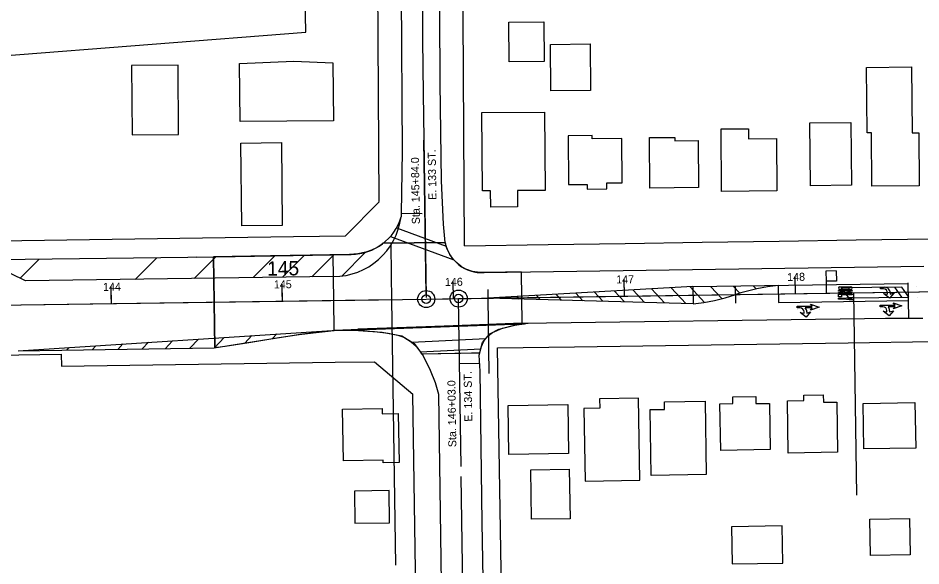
# Model space of a CAD drawing. Extents: x -2233 to 187241, y 4582 to 150524.
# Drawn here: x 114288 to 114816, y 59403 to 59724 of the extents above; entities that cross this region are included whole.
import ezdxf

# ---------------------------------------------------------------- set-up
doc = ezdxf.new("R2010")
doc.units = 0
for name, color, linetype in [('AP_X_Misc', 7, 'Continuous'), ('BLDG', 7, 'Continuous'), ('GE_X_CL_100', 7, 'Continuous'), ('GE_X_CL_20', 7, 'Continuous'), ('GE_X_CL_2000', 7, 'Continuous'), ('GE_X_CL_50', 7, 'Continuous'), ('PM_P_Cells', 7, 'Continuous'), ('PM_P_Channelizing_Line', 7, 'Continuous'), ('PM_P_CL_Double_Solid', 7, 'Continuous'), ('PM_P_Crosswalk', 7, 'Continuous'), ('PM_P_Edge_Line', 7, 'Continuous'), ('PM_P_Stop_Line', 7, 'Continuous'), ('PM_P_Text', 7, 'Continuous'), ('PM_P_Transverse_Line', 7, 'Continuous'), ('ROAD', 7, 'Continuous'), ('RW_X_Fee_RW', 7, 'Continuous'), ('SG_P_Detection', 7, 'Continuous')]:
    doc.layers.add(name, color=color, linetype=linetype)

msp = doc.modelspace()

# ---------------------------------------------------------------- linework, layer by layer
at = {"layer": 'AP_X_Misc'}
for p, q in [((114472.32, 59558.35), (114471.93, 59585.11)), ((114402.33, 59557.33), (114401.95, 59583.84)), ((114582.31, 59559.94), (114582.09, 59574.94)), ((114472.58, 59540.94), (114472.32, 59558.35)), ((114582.53, 59544.95), (114582.31, 59559.94)), ((114402.72, 59530.83), (114402.33, 59557.33)), ((114582.53, 59544.95), (114472.58, 59540.82))]:
    msp.add_line(p, q, dxfattribs=at)
for points in [[(114276.11, 59701.18), (114455.92, 59715.3), (114455.49, 59745.29), (114275.34, 59754.19)], [(114401.95, 59583.84), (114402.72, 59530.83), (114408.87, 59531.56), (114422.61, 59533.76), (114440.22, 59536.58), (114452.12, 59538.49), (114460.21, 59539.47), (114468.99, 59540.43), (114472.58, 59540.94), (114481.11, 59540.9), (114582.87, 59544.58), (114582.53, 59544.95), (114582.09, 59574.94), (114579.6, 59574.91), (114572.67, 59574.81), (114568.04, 59574.74), (114564.56, 59574.69), (114560.95, 59574.64), (114557.75, 59574.62), (114553.49, 59575.28), (114549.52, 59576.72), (114546.88, 59578.21), (114545.17, 59579.46), (114542.26, 59582.29), (114540.21, 59585.14), (114538.58, 59588.41), (114537.78, 59590.81), (114537.44, 59592.3), (114501.27, 59591.77), (114499.92, 59590.77), (114497.78, 59589.4), (114494.48, 59587.74), (114491.14, 59586.54), (114486.32, 59585.54), (114481.54, 59585.29), (114423.85, 59584.24)], [(114486.36, 59541.45), (114490.22, 59540.54), (114496.16, 59540.07), (114504.05, 59539.09), (114509.8, 59538.02), (114513.28, 59536.87), (114517.62, 59534.17), (114520.45, 59531.58), (114522.94, 59528.1), (114523.62, 59527.16), (114543.18, 59527.45), (114552.92, 59527.59), (114557.69, 59527.66), (114558.52, 59531), (114560.22, 59534.89), (114562.51, 59537.57), (114565.19, 59539.63), (114570.94, 59542.04), (114577.87, 59543.79), (114583.77, 59544.7), (114581.4, 59544.9), (114558.08, 59544.06), (114526.2, 59542.9)]]:
    msp.add_lwpolyline(points, close=True, dxfattribs=at)
at = {"layer": 'BLDG'}
for points in [[(114595.15, 59721.38), (114595.35, 59698.14), (114574.94, 59697.96), (114574.74, 59721.2)], [(114622.26, 59708.4), (114622.5, 59681.11), (114599.24, 59680.9), (114599.01, 59708.19)], [(114381.65, 59655.38), (114381.29, 59696.05), (114354.17, 59695.82), (114354.53, 59655.15)], [(114417.26, 59696.94), (114448.94, 59698.41), (114471.84, 59697.41), (114472.14, 59663.51), (114417.55, 59663.04)], [(114810.12, 59694.93), (114810.45, 59656.46), (114814.27, 59656.49), (114814.55, 59625.36), (114786.96, 59625.12), (114786.68, 59656.5), (114784.12, 59656.48), (114783.79, 59694.71)], [(114595.55, 59668.54), (114595.95, 59622.74), (114579.65, 59622.6), (114579.73, 59613.06), (114564.11, 59612.92), (114564.02, 59622.53), (114559.29, 59622.49), (114558.89, 59668.22)], [(114714.77, 59658.81), (114714.82, 59652.97), (114731.05, 59653.11), (114731.32, 59622.45), (114699.07, 59622.17), (114698.75, 59658.67)], [(114774.61, 59662.48), (114774.93, 59625.7), (114750.96, 59625.49), (114750.64, 59662.27)], [(114620.44, 59626.26), (114620.47, 59623.49), (114631.95, 59623.59), (114631.92, 59627.13), (114641.01, 59627.21), (114640.79, 59653.1), (114623.41, 59652.94), (114623.39, 59654.78), (114609.33, 59654.66), (114609.58, 59626.16)], [(114671.75, 59653.74), (114671.77, 59651.79), (114685.26, 59651.9), (114685.5, 59624.36), (114657.07, 59624.12), (114656.81, 59653.61)], [(114441.78, 59650.66), (114442.2, 59602.23), (114418.5, 59602.02), (114418.07, 59650.45)], [(114627.77, 59500.82), (114627.85, 59495.27), (114618.53, 59495.12), (114619.23, 59452.55), (114651.24, 59453.07), (114650.46, 59501.18)], [(114698.11, 59497.88), (114705.59, 59498), (114705.53, 59501.95), (114719.09, 59502.18), (114719.15, 59497.95), (114727.07, 59498.08), (114727.52, 59471.08), (114698.56, 59470.6)], [(114737.54, 59499.53), (114747.21, 59499.7), (114747.15, 59502.86), (114758.47, 59503.05), (114758.54, 59498.76), (114766.37, 59498.89), (114766.84, 59469.51), (114738.04, 59469.04)], [(114500.63, 59495.15), (114500.68, 59492.04), (114510, 59492.19), (114510.47, 59463.46), (114501.19, 59463.31), (114501.16, 59464.95), (114477.97, 59464.57), (114477.47, 59494.76)], [(114574.25, 59496.87), (114609.07, 59497.44), (114609.54, 59468.84), (114574.72, 59468.26)], [(114665.75, 59494.57), (114665.67, 59499.07), (114689.36, 59499.45), (114690.06, 59456.48), (114657.9, 59455.95), (114657.27, 59494.42)], [(114781.78, 59498.09), (114812.07, 59498.58), (114812.5, 59471.98), (114782.21, 59471.47)], [(114610.02, 59459.62), (114610.49, 59430.63), (114587.97, 59430.27), (114587.5, 59459.25)], [(114484.71, 59427.91), (114504.98, 59428.25), (114504.68, 59447.14), (114484.4, 59446.81)], [(114705.22, 59404.12), (114734.76, 59404.6), (114734.4, 59426.43), (114704.86, 59425.95)], [(114808.94, 59430.72), (114809.29, 59409.52), (114786.06, 59409.13), (114785.72, 59430.34)]]:
    msp.add_lwpolyline(points, close=True, dxfattribs=at)
at = {"layer": 'GE_X_CL_100'}
for p, q in [((114542.32, 59559.36), (114542.17, 59569.36)), ((114642.3, 59560.82), (114642.16, 59570.81)), ((114742.29, 59562.27), (114742.15, 59572.27)), ((114342.34, 59556.46), (114342.19, 59566.46)), ((114442.33, 59557.91), (114442.18, 59567.91))]:
    msp.add_line(p, q, dxfattribs=at)
for centre in [(114526.38, 59559.13), (114545.33, 59559.41), (114545.33, 59559.41)]:
    msp.add_circle(centre, 5, dxfattribs=at)
at = {"layer": 'GE_X_CL_20'}
for p, q in [((114524.63, 59679.24), (114526.36, 59560.13)), ((114545.33, 59559.41), (114849.04, 59563.82)), ((114245.36, 59555.05), (114526.38, 59559.13)), ((114526.38, 59559.13), (114545.33, 59559.41)), ((114547.8, 59389), (114546.84, 59455.37))]:
    msp.add_line(p, q, dxfattribs=at)
at = {"layer": 'GE_X_CL_2000'}
for p, q in [((114526.38, 59559.13), (114849.04, 59563.82)), ((114245.36, 59555.05), (114526.38, 59559.13))]:
    msp.add_line(p, q, dxfattribs=at)
msp.add_lwpolyline([(114524.39, 59750.36), (114524.15, 59710.86), (114524.63, 59679.24)], dxfattribs=at)
at = {"layer": 'GE_X_CL_50'}
for p, q in [((114526.34, 59561.63), (114525.03, 59652.14)), ((114442.33, 59557.91), (114442.25, 59562.91)), ((114542.32, 59559.36), (114542.24, 59564.36)), ((114642.3, 59560.82), (114642.23, 59565.82)), ((114742.29, 59562.27), (114742.22, 59567.27)), ((114342.34, 59556.46), (114342.26, 59561.46)), ((114546.75, 59461.13), (114545.33, 59559.41))]:
    msp.add_line(p, q, dxfattribs=at)
for centre in [(114526.38, 59559.13), (114545.33, 59559.41), (114545.33, 59559.41)]:
    msp.add_circle(centre, 2.5, dxfattribs=at)
at = {"layer": 'PM_P_Cells'}
for p, q in [((114767.39, 59563.71), (114767.39, 59564.21)), ((114767.39, 59564.21), (114775.39, 59564.21)), ((114767.39, 59563.05), (114771.14, 59563.71)), ((114771.14, 59563.71), (114767.39, 59563.71)), ((114767.39, 59562.55), (114767.39, 59563.05)), ((114768.22, 59566.38), (114769.39, 59566.38)), ((114774.55, 59564.71), (114768.22, 59564.71)), ((114769.39, 59566.38), (114769.39, 59565.88)), ((114769.39, 59565.88), (114769.39, 59566.38)), ((114769.39, 59566.38), (114773.39, 59566.38)), ((114773.39, 59565.88), (114769.39, 59565.88)), ((114769.39, 59565.21), (114773.39, 59565.21)), ((114775.39, 59563.71), (114771.64, 59563.05)), ((114771.64, 59563.05), (114775.39, 59563.05)), ((114773.39, 59565.88), (114773.39, 59566.38)), ((114773.39, 59566.38), (114774.55, 59566.38)), ((114773.39, 59566.38), (114773.39, 59565.88)), ((114775.39, 59564.21), (114775.39, 59563.71)), ((114775.39, 59563.05), (114775.39, 59562.55)), ((114791.86, 59565.03), (114791.86, 59566.03)), ((114791.86, 59566.03), (114794.34, 59566.03)), ((114793.73, 59565.03), (114791.86, 59565.03)), ((114775.39, 59562.55), (114767.39, 59562.55)), ((114767.39, 59562.46), (114767.39, 59562.46)), ((114767.39, 59560.38), (114767.39, 59562.05)), ((114767.39, 59562.05), (114775.39, 59562.05)), ((114769.05, 59560.38), (114767.39, 59560.38)), ((114767.39, 59559.13), (114767.39, 59559.63)), ((114767.39, 59559.63), (114770.39, 59559.63)), ((114770.39, 59559.13), (114767.39, 59559.13)), ((114775.39, 59561.55), (114769.05, 59561.55)), ((114769.05, 59561.55), (114769.05, 59560.38)), ((114770.39, 59559.63), (114775.39, 59560.21)), ((114775.39, 59558.55), (114770.39, 59559.13)), ((114775.39, 59559.71), (114772.72, 59559.38)), ((114772.72, 59559.38), (114775.39, 59559.05)), ((114775.39, 59562.46), (114775.39, 59562.46)), ((114775.39, 59562.05), (114775.39, 59561.55)), ((114775.39, 59560.21), (114775.39, 59559.71)), ((114775.39, 59559.05), (114775.39, 59558.55)), ((114791.86, 59562.7), (114791.86, 59562.7)), ((114797.3, 59559.7), (114793.78, 59562.36)), ((114793.78, 59562.36), (114796.02, 59562.03)), ((114796.02, 59562.03), (114796.02, 59562.73)), ((114799.86, 59562.7), (114797.3, 59559.7)), ((114797.62, 59562.7), (114797.62, 59562.03)), ((114797.62, 59562.03), (114799.86, 59562.7)), ((114799.86, 59562.7), (114799.86, 59562.7)), ((114743.27, 59553.91), (114743.27, 59554.91)), ((114743.27, 59554.91), (114752.02, 59554.91)), ((114744.95, 59553.91), (114743.27, 59553.91)), ((114743.27, 59552.74), (114743.27, 59552.74)), ((114752.02, 59554.91), (114751.02, 59556.15)), ((114751.02, 59556.15), (114756.02, 59554.41)), ((114756.02, 59554.41), (114751.02, 59552.68)), ((114751.02, 59552.68), (114752.02, 59553.91)), ((114756.02, 59552.74), (114756.02, 59552.74)), ((114791.69, 59554.65), (114791.69, 59555.65)), ((114791.69, 59555.65), (114800.44, 59555.65)), ((114793.36, 59554.65), (114791.69, 59554.65)), ((114791.69, 59553.49), (114791.69, 59553.49)), ((114795.66, 59551.65), (114795.66, 59552.36)), ((114799.5, 59552.32), (114796.94, 59549.32)), ((114797.26, 59552.32), (114797.26, 59551.65)), ((114797.26, 59551.65), (114799.5, 59552.32)), ((114800.44, 59555.65), (114799.44, 59556.89)), ((114799.44, 59556.89), (114804.44, 59555.15)), ((114804.44, 59555.15), (114799.44, 59553.42)), ((114799.44, 59553.42), (114800.44, 59554.65)), ((114804.44, 59553.49), (114804.44, 59553.49)), ((114748.52, 59548.58), (114745, 59551.24)), ((114745, 59551.24), (114747.24, 59550.91)), ((114747.24, 59550.91), (114747.24, 59551.61)), ((114751.08, 59551.58), (114748.52, 59548.58)), ((114748.84, 59551.58), (114748.84, 59550.91)), ((114748.84, 59550.91), (114751.08, 59551.58)), ((114796.94, 59549.32), (114793.42, 59551.99)), ((114793.42, 59551.99), (114795.66, 59551.65))]:
    msp.add_line(p, q, dxfattribs=at)
for points in [[(114752.02, 59553.91), (114747.92, 59553.91)], [(114800.44, 59554.65), (114796.34, 59554.65)]]:
    msp.add_lwpolyline(points, dxfattribs=at)
for centre, radius, start, end in [((114768.22, 59565.55), 0.833, 90, 270), ((114769.39, 59565.55), 0.333, 90, 270), ((114773.39, 59565.55), 0.333, 270, 90), ((114774.55, 59565.55), 0.833, 270, 90), ((114793.73, 59562.73), 2.3, 0, 90), ((114794.34, 59562.75), 3.28, 359.0915, 90), ((114744.95, 59551.61), 2.3, 0, 90), ((114745.56, 59551.63), 3.28, 359.0915, 44.0466), ((114793.36, 59552.36), 2.3, 0, 90), ((114793.98, 59552.37), 3.28, 359.0915, 44.0466)]:
    msp.add_arc(centre, radius, start, end, dxfattribs=at)
at = {"layer": 'PM_P_Channelizing_Line'}
msp.add_line((114732.35, 59557.12), (114808.36, 59558.23), dxfattribs=at)
at = {"layer": 'PM_P_CL_Double_Solid'}
for p, q in [((114682.21, 59566.4), (114808.21, 59568.23)), ((114682.21, 59566.4), (114562.42, 59559.66)), ((114245.36, 59555.05), (114506.32, 59558.84)), ((114682.36, 59556.4), (114562.42, 59559.66))]:
    msp.add_line(p, q, dxfattribs=at)
for centre, radius, start, end in [((114744.29, 59450.37), 117.38, 95.9071, 108.3766), ((114674.1, 59655.38), 99.33, 274.7684, 289.5154)]:
    msp.add_arc(centre, radius, start, end, dxfattribs=at)
at = {"layer": 'PM_P_Crosswalk'}
for p, q in [((114508.99, 59600.83), (114537.95, 59590.1)), ((114505.43, 59595.74), (114542.5, 59582.01)), ((114517.97, 59533.95), (114561.23, 59536.07)), ((114522.89, 59528.18), (114558.26, 59529.92))]:
    msp.add_line(p, q, dxfattribs=at)
at = {"layer": 'PM_P_Edge_Line'}
for p, q in [((114292.14, 59569.73), (114266.96, 59581.99)), ((114472.12, 59572.35), (114292.14, 59569.73)), ((114287.78, 59528.86), (114474.34, 59541.01))]:
    msp.add_line(p, q, dxfattribs=at)
msp.add_arc((114472.29, 59611.98), 39.63, 269.7477, 353.1607, dxfattribs=at)
at = {"layer": 'PM_P_Stop_Line'}
for p, q in [((114511.68, 59609.41), (114523.95, 59609.19)), ((114808.51, 59548.01), (114808.21, 59568.72)), ((114557.8, 59521.44), (114545.57, 59521.28))]:
    msp.add_line(p, q, dxfattribs=at)
at = {"layer": 'PM_P_Text'}
for p, q in [((114506.12, 59572.84), (114505.84, 59591.64)), ((114506.32, 59558.84), (114506.12, 59572.84)), ((114760.15, 59569.53), (114760.25, 59562.53)), ((114562.35, 59564.65), (114562.42, 59559.66)), ((114682.21, 59566.4), (114682.36, 59556.4)), ((114707.35, 59556.76), (114707.21, 59566.76)), ((114732.21, 59567.12), (114732.35, 59557.12)), ((114508.58, 59403.38), (114506.32, 59558.84)), ((114562.42, 59559.66), (114563.06, 59515.54)), ((114682.28, 59561.4), (114707.28, 59561.76)), ((114776.25, 59562.76), (114777.97, 59444.32))]:
    msp.add_line(p, q, dxfattribs=at)
at = {"layer": 'PM_P_Transverse_Line'}
for p, q in [((114425.14, 59571.66), (114437.97, 59584.49)), ((114442.36, 59571.91), (114455.26, 59584.81)), ((114459.58, 59572.16), (114472.54, 59585.13)), ((114477.01, 59572.63), (114490.87, 59586.49)), ((114288.98, 59571.27), (114300.12, 59582.41)), ((114356.26, 59570.66), (114368.87, 59583.28)), ((114390.7, 59571.16), (114403.4, 59583.86)), ((114624.71, 59563.16), (114629.64, 59557.83)), ((114636.42, 59563.82), (114642.27, 59557.49)), ((114647.32, 59564.43), (114654.04, 59557.17)), ((114658.14, 59565.04), (114665.71, 59556.85)), ((114669.64, 59565.69), (114678.13, 59556.51)), ((114680.65, 59566.31), (114689.09, 59557.19)), ((114692.65, 59566.55), (114699.34, 59559.31)), ((114705.74, 59566.74), (114709.65, 59562.52)), ((114717.59, 59566.91), (114719.31, 59565.06)), ((114579.36, 59560.61), (114580.71, 59559.16)), ((114590.78, 59561.25), (114593.02, 59558.82)), ((114602.28, 59561.9), (114605.44, 59558.49)), ((114613.8, 59562.55), (114617.86, 59558.15)), ((114402.53, 59530.54), (114408.23, 59536.71)), ((114420.36, 59533.4), (114424.39, 59537.76)), ((114436.59, 59536), (114439.1, 59538.72)), ((114331.16, 59529.49), (114333.32, 59531.83)), ((114346.1, 59529.71), (114349.01, 59532.85)), ((114360.34, 59529.92), (114363.95, 59533.82)), ((114373.83, 59530.11), (114378.11, 59534.74)), ((114388.22, 59530.32), (114393.22, 59535.73)), ((114316.3, 59529.28), (114317.72, 59530.81))]:
    msp.add_line(p, q, dxfattribs=at)
at = {"layer": 'ROAD'}
for p, q in [((114501.27, 59591.77), (114537.44, 59592.3)), ((114392.12, 59583.66), (114482.57, 59585.31)), ((114560.18, 59574.62), (114817.26, 59578.36)), ((114582.53, 59544.95), (114782.51, 59547.85)), ((114474.34, 59541.01), (114582.53, 59544.95)), ((114578.93, 59544.05), (114585.95, 59545)), ((114287.78, 59528.86), (114402.46, 59530.53)), ((114523.62, 59527.16), (114557.69, 59527.66))]:
    msp.add_line(p, q, dxfattribs=at)
for points in [[(114537.44, 59592.3), (114536.51, 59602.94), (114535.3, 59628.35), (114534.44, 59685.43), (114534.19, 59768.17)], [(114511.67, 59737.78), (114512.35, 59645.41), (114511.68, 59609.41)], [(114511.68, 59609.41), (114511.64, 59607.26)], [(114387.06, 59583.51), (114212.36, 59581.3), (113959.02, 59576.76), (113803.88, 59575.29), (113753.8, 59574.59)], [(114392.12, 59583.66), (114387.06, 59583.51)], [(114782.51, 59547.78), (114794.84, 59548), (114816.62, 59548.03)], [(114566.67, 58944.14), (114565.62, 59041.4), (114563.41, 59159.74), (114561.42, 59296.43), (114558.99, 59428.36), (114557.85, 59516.93), (114557.37, 59526.37), (114559.2, 59533.69), (114563.52, 59538.76), (114568.78, 59541.5), (114578.93, 59544.05)], [(114402.46, 59530.53), (114454, 59538.79), (114474.34, 59541.01), (114486.73, 59540.81), (114500.69, 59539.72), (114512.14, 59537.58), (114519.39, 59533.06), (114524.51, 59525.92), (114528.63, 59517.53), (114531.63, 59510.39), (114533.56, 59503.5), (114535.66, 59351.49), (114538.12, 59196.14), (114541.93, 58969.52)]]:
    msp.add_lwpolyline(points, dxfattribs=at)
for centre, radius, start, end in [((114482.6, 59615.5), 30.19, 269.9417, 344.1643), ((114558.94, 59596.49), 21.9, 191.0394, 273.2493)]:
    msp.add_arc(centre, radius, start, end, dxfattribs=at)
at = {"layer": 'RW_X_Fee_RW'}
for p, q in [((114268.06, 59526.15), (114313.06, 59526.81)), ((114313.06, 59526.81), (114313.18, 59519.81)), ((114496.16, 59522.49), (114518.48, 59503.42))]:
    msp.add_line(p, q, dxfattribs=at)
for points in [[(114548.82, 59590.31), (114547.99, 59724.71), (114547.74, 59764.71), (114547.5, 59804.71), (114547.25, 59844.71), (114547, 59884.7), (114546.76, 59924.7), (114546.51, 59964.7), (114546.26, 60004.7)], [(114496.34, 59993.13), (114395.86, 59990.59), (114306.2, 59899.2), (114224.5, 59841.42), (114149.67, 59774.14), (114089.58, 59687.64), (114157.41, 59640.5), (114157.7, 59591.37), (114408.78, 59595.23), (114448.78, 59595.82), (114479.28, 59596.13), (114498.82, 59616.05)], [(114496.33, 59993.16), (114497.57, 59793.49), (114497.87, 59743.49), (114498.66, 59616.19)], [(114548.82, 59590.31), (114597.72, 59591.04), (114642.72, 59591.71), (114687.72, 59592.38), (114732.71, 59593.05), (114777.71, 59593.72), (114822.7, 59594.39)], [(114568.05, 59530.55), (114613.05, 59531.21), (114653.04, 59531.8), (114693.04, 59532.38), (114733.04, 59532.97), (114773.04, 59533.56), (114823.03, 59534.29)], [(114585.89, 58437.78), (114583.97, 58555.68), (114583.23, 58600.67), (114582.5, 58645.66), (114581.76, 58690.66), (114581.03, 58735.65), (114580.3, 58780.65), (114579.56, 58825.64), (114578.83, 58870.63), (114578.09, 58915.63), (114577.36, 58960.62), (114576.62, 59005.62), (114575.89, 59050.61), (114575.15, 59095.61), (114574.42, 59140.6), (114573.68, 59185.59), (114572.95, 59230.59), (114572.21, 59275.58), (114571.48, 59320.58), (114570.82, 59360.57), (114570.17, 59400.57), (114568.05, 59530.55)], [(114313.18, 59519.81), (114353.17, 59520.4), (114393.17, 59520.98), (114433.17, 59521.57), (114473.16, 59522.16), (114496.16, 59522.49)], [(114535.91, 58436.2), (114534.13, 58545.35), (114533.4, 58590.34), (114532.66, 58635.34), (114531.93, 58680.33), (114531.19, 58725.33), (114530.46, 58770.32), (114529.72, 58815.31), (114528.99, 58860.31), (114528.25, 58905.3), (114527.52, 58950.3), (114526.78, 58995.29), (114526.05, 59040.28), (114525.31, 59085.28), (114524.58, 59130.27), (114523.84, 59175.27), (114523.11, 59220.26), (114522.37, 59265.26), (114521.64, 59310.25), (114520.9, 59355.24), (114520.17, 59400.24), (114518.48, 59503.42)]]:
    msp.add_lwpolyline(points, dxfattribs=at)
at = {"layer": 'SG_P_Detection'}
for p, q in [((114766.06, 59575.61), (114760.07, 59575.53)), ((114760.07, 59575.53), (114760.15, 59569.53)), ((114766.06, 59575.61), (114766.15, 59569.61)), ((114766.15, 59569.61), (114760.15, 59569.53)), ((114804.41, 59566.16), (114769.41, 59565.77)), ((114773.48, 59559.81), (114769.41, 59565.77)), ((114776.21, 59565.76), (114776.21, 59565.76)), ((114804.48, 59560.16), (114800.41, 59566.12)), ((114808.48, 59560.21), (114804.41, 59566.16)), ((114813.21, 59566.3), (114813.21, 59566.3)), ((114773.48, 59559.81), (114808.48, 59560.21)), ((114776.3, 59559.76), (114776.3, 59559.76)), ((114813.29, 59560.3), (114813.29, 59560.3))]:
    msp.add_line(p, q, dxfattribs=at)

# ---------------------------------------------------------------- texts
at = {"layer": 'GE_X_CL_100'}
msp.add_text('145', height=8.4, rotation=0.8319, dxfattribs=at).set_placement((114433.4, 59572.78))
at = {"layer": 'GE_X_CL_50'}
for s, rotation, p in [('E. 133 ST.', 90.8319, (114532.36, 59617.18)), ('Sta. 145+84.0', 90.8319, (114522.69, 59602.98)), ('148', 0.8319, (114737.41, 59569.7)), ('144', 0.8319, (114337.46, 59563.89)), ('145', 0.8319, (114437.35, 59565.34)), ('146', 0.8319, (114537.33, 59566.79)), ('147', 0.8319, (114637.46, 59568.25)), ('E. 134 ST.', 90.8319, (114553.36, 59487.41)), ('Sta. 146+03.0', 90.8319, (114543.99, 59472.5))]:
    msp.add_text(s, height=4.68, rotation=rotation, dxfattribs=at).set_placement(p)

doc.saveas('drawing.dxf')
